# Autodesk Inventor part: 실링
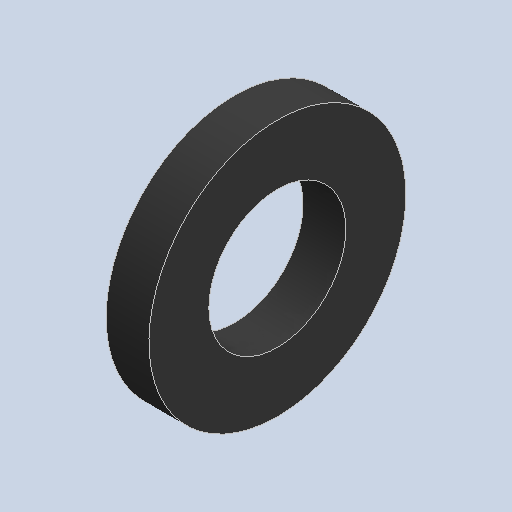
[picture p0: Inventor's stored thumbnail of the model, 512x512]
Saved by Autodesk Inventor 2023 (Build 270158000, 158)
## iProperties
Created: 2026-03
Part Number: 실링
Material: 고무, 실리콘
Document SubType Name: Modeling
Designer: 4강의실
Density: 1.25 g/cm^3
Appearance: 기본값
Author: jhkim
Sending System: Autodesk Inventor 2026
Preprocessor: ST-DEVELOPER v20.1
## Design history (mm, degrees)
feature "솔리드1"
node "솔리드2"
